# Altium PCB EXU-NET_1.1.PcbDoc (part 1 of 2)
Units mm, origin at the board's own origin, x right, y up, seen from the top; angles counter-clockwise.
Board outline 89 x 74.45 mm, 4 copper layers (Top Layer, Layer 1, Layer 2, Bottom Layer), stack 1.57 mm thick; 116 components, 84 nets, 406 pads, 488 vias.
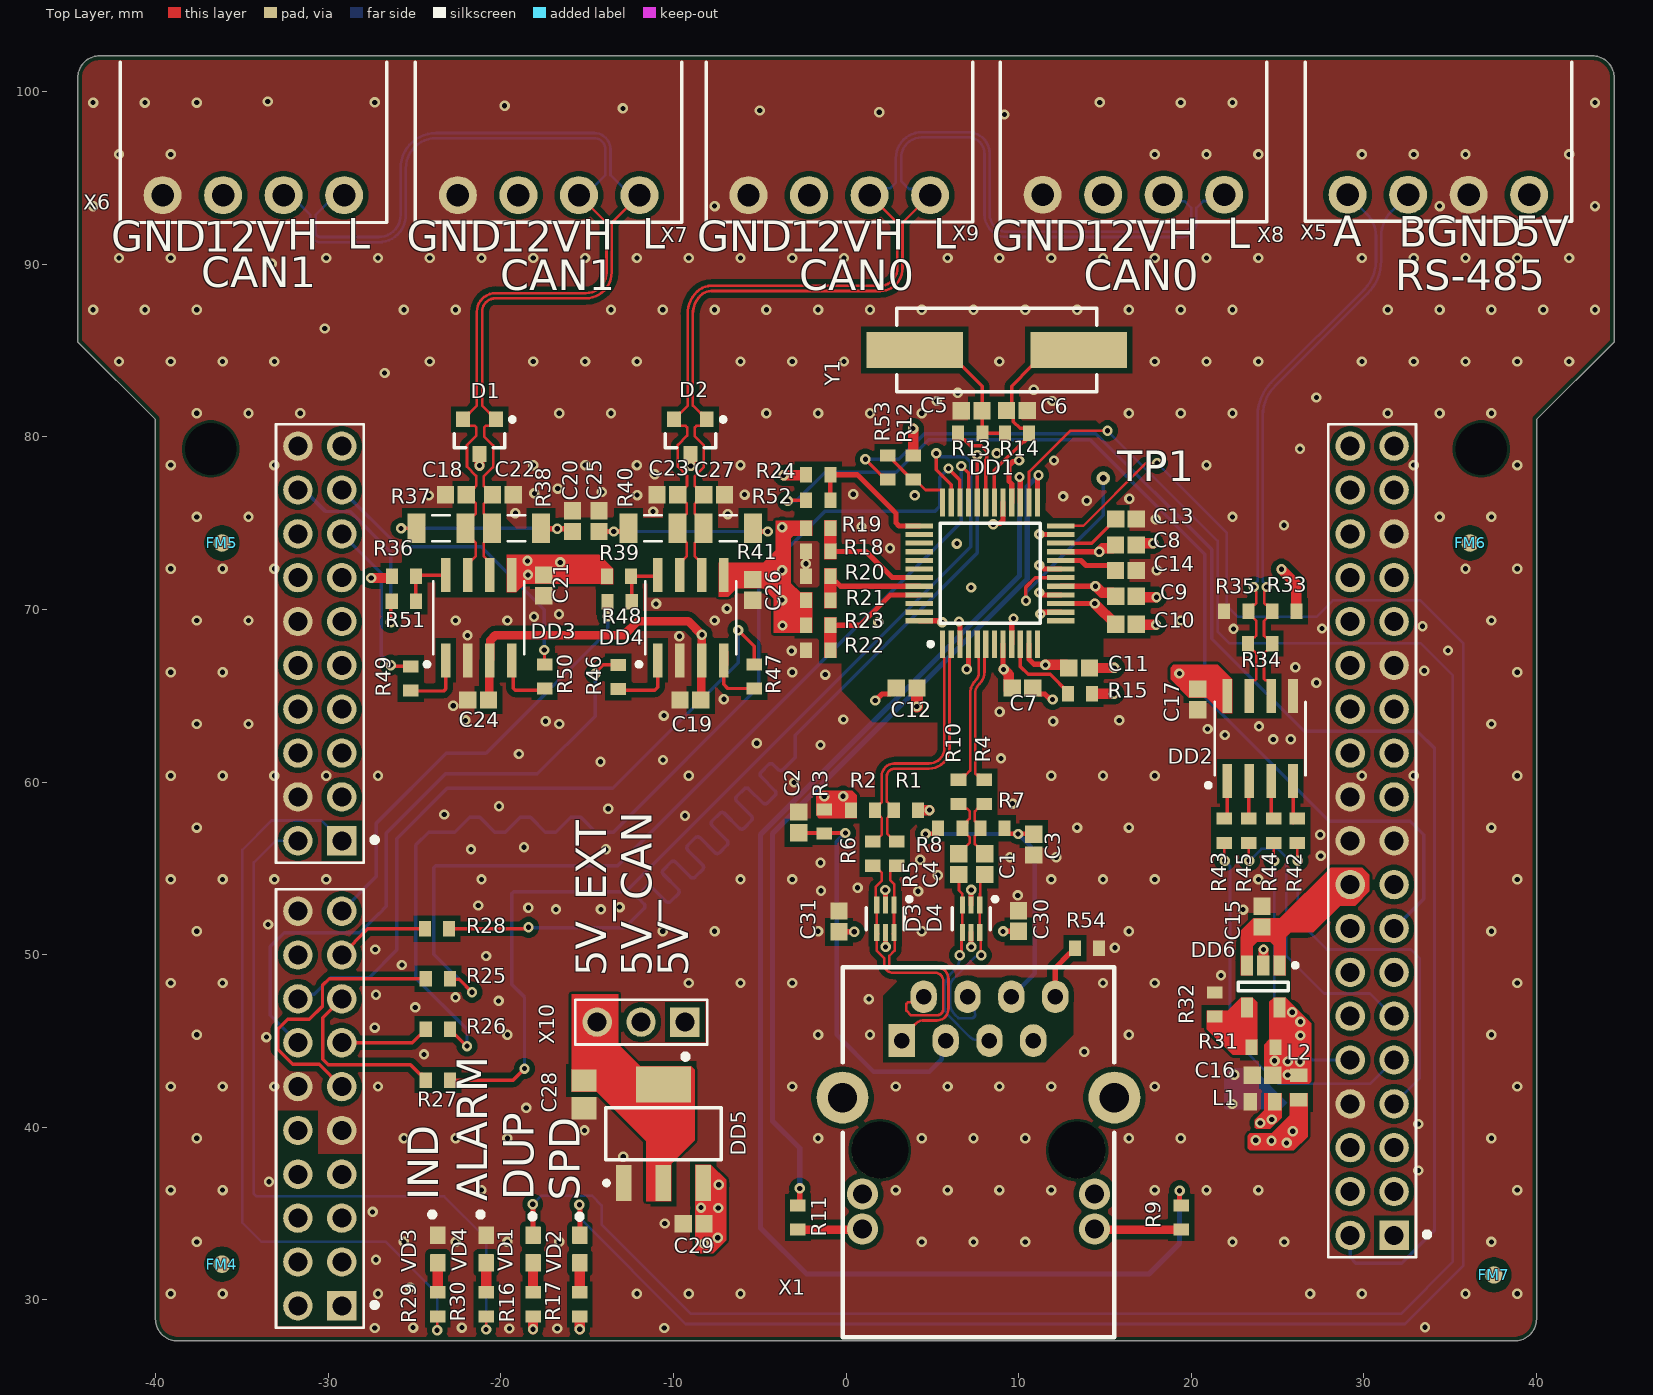
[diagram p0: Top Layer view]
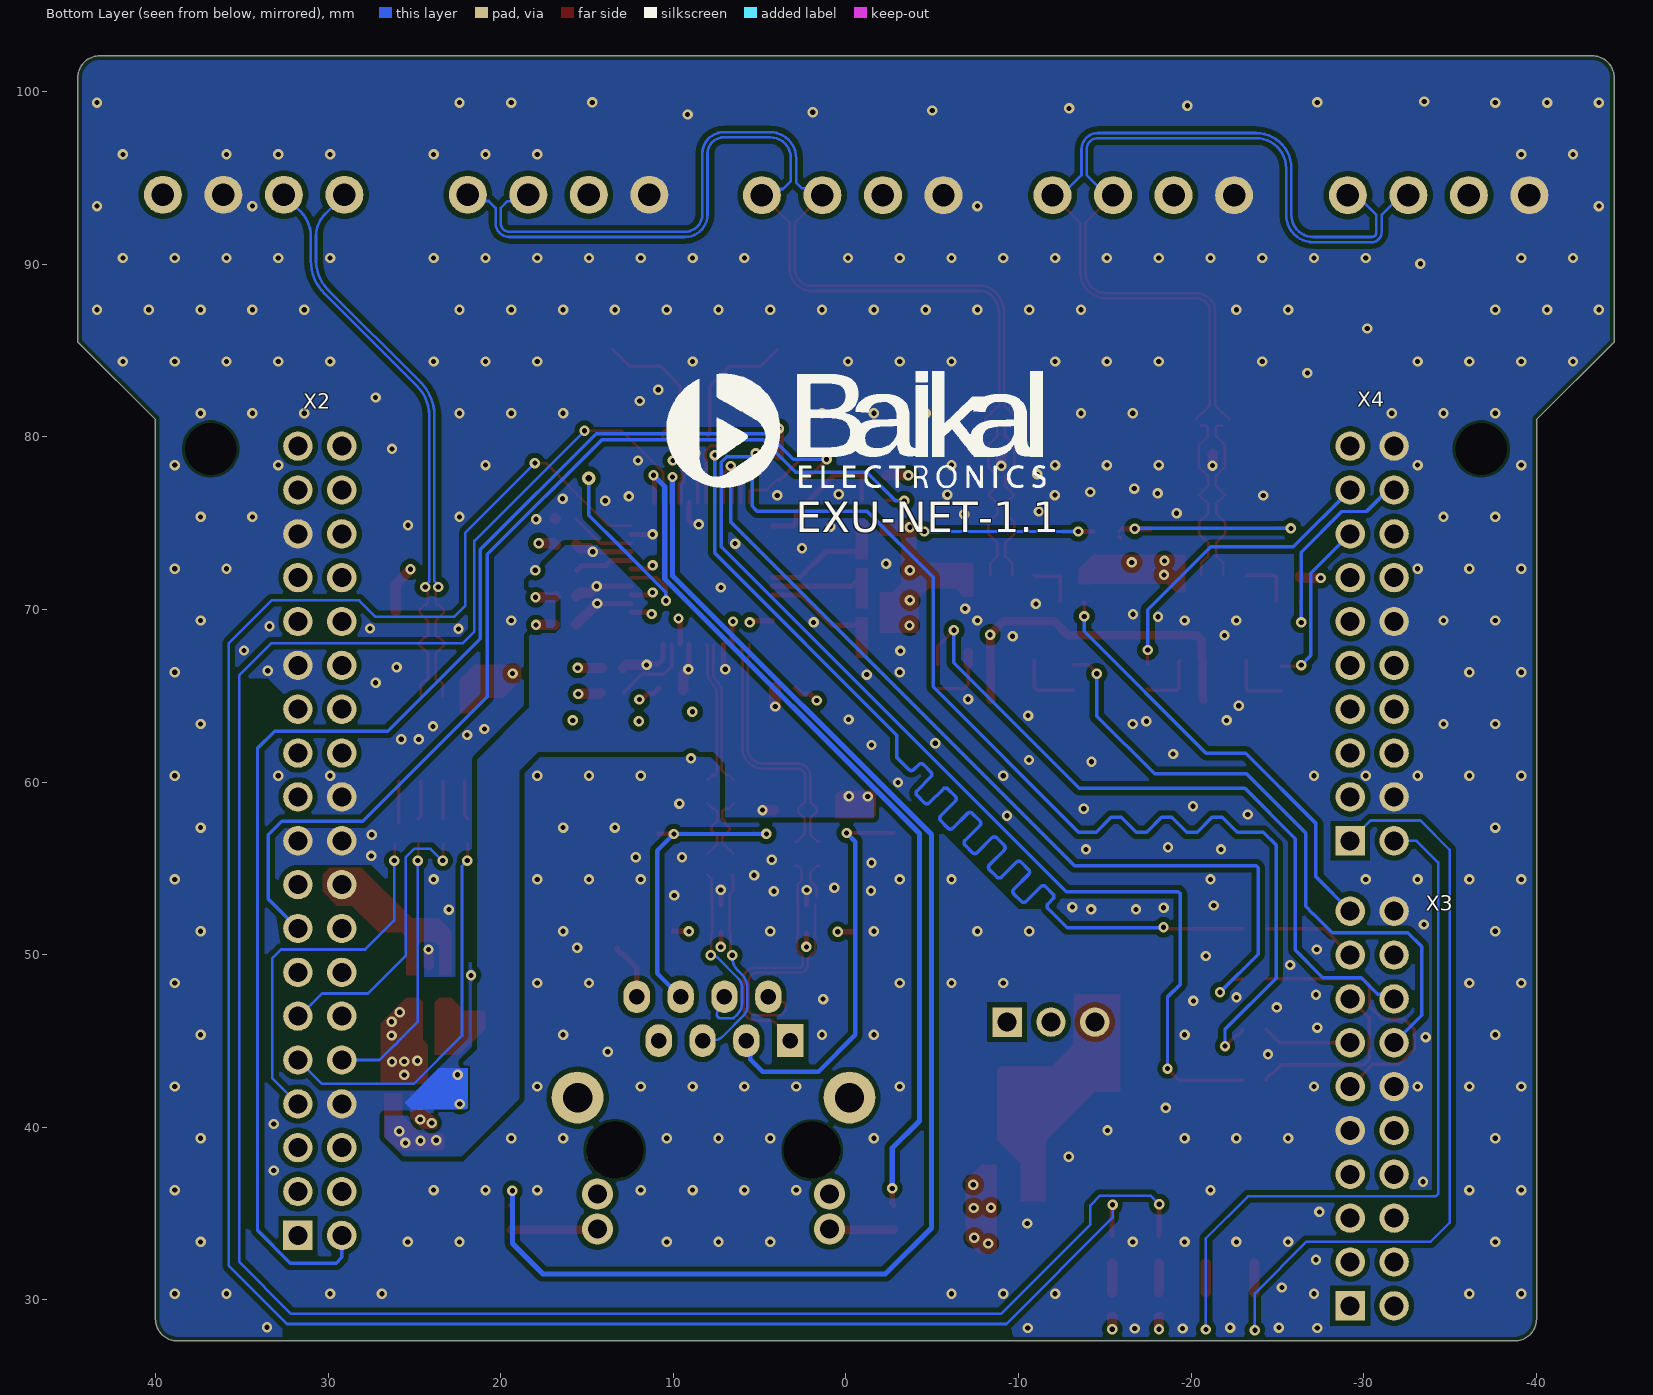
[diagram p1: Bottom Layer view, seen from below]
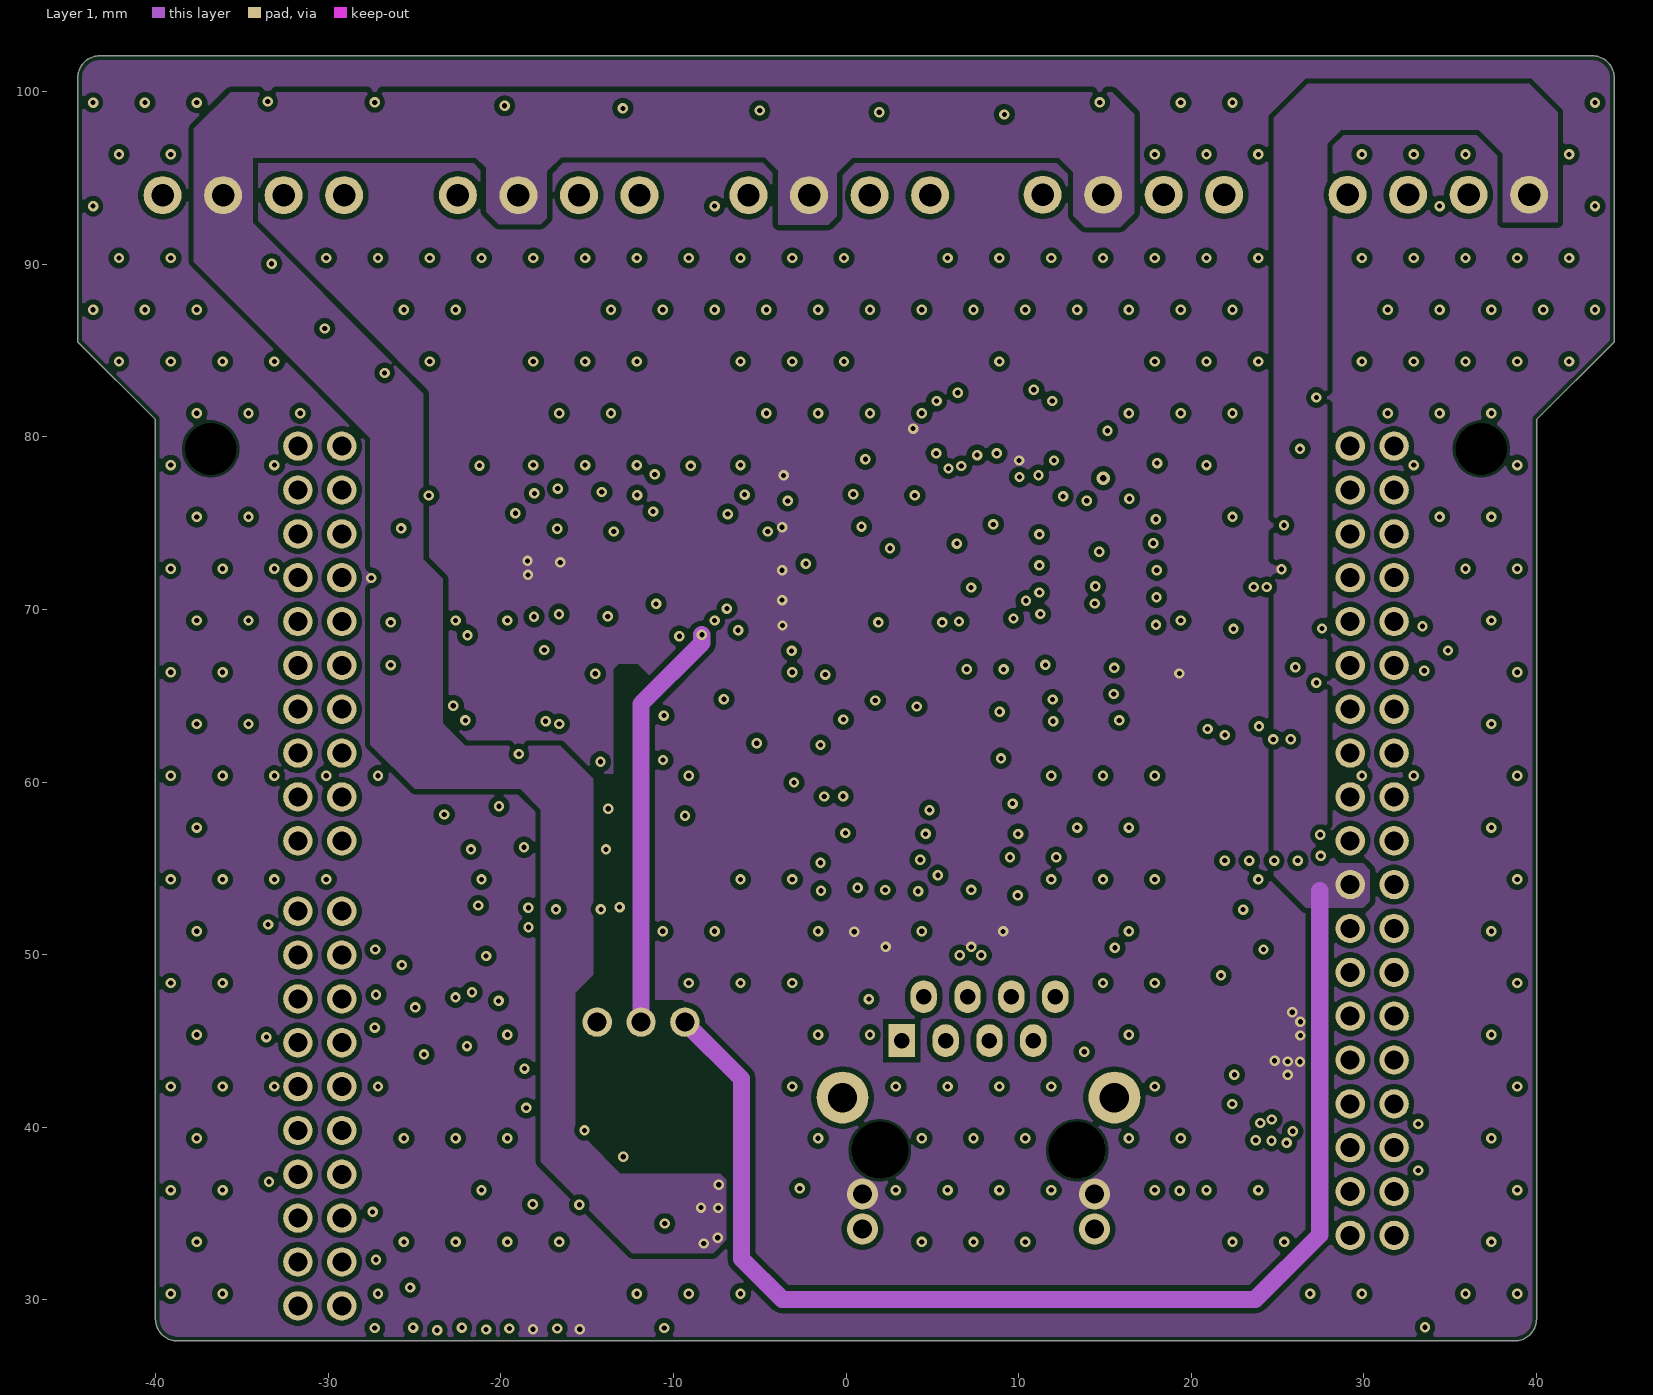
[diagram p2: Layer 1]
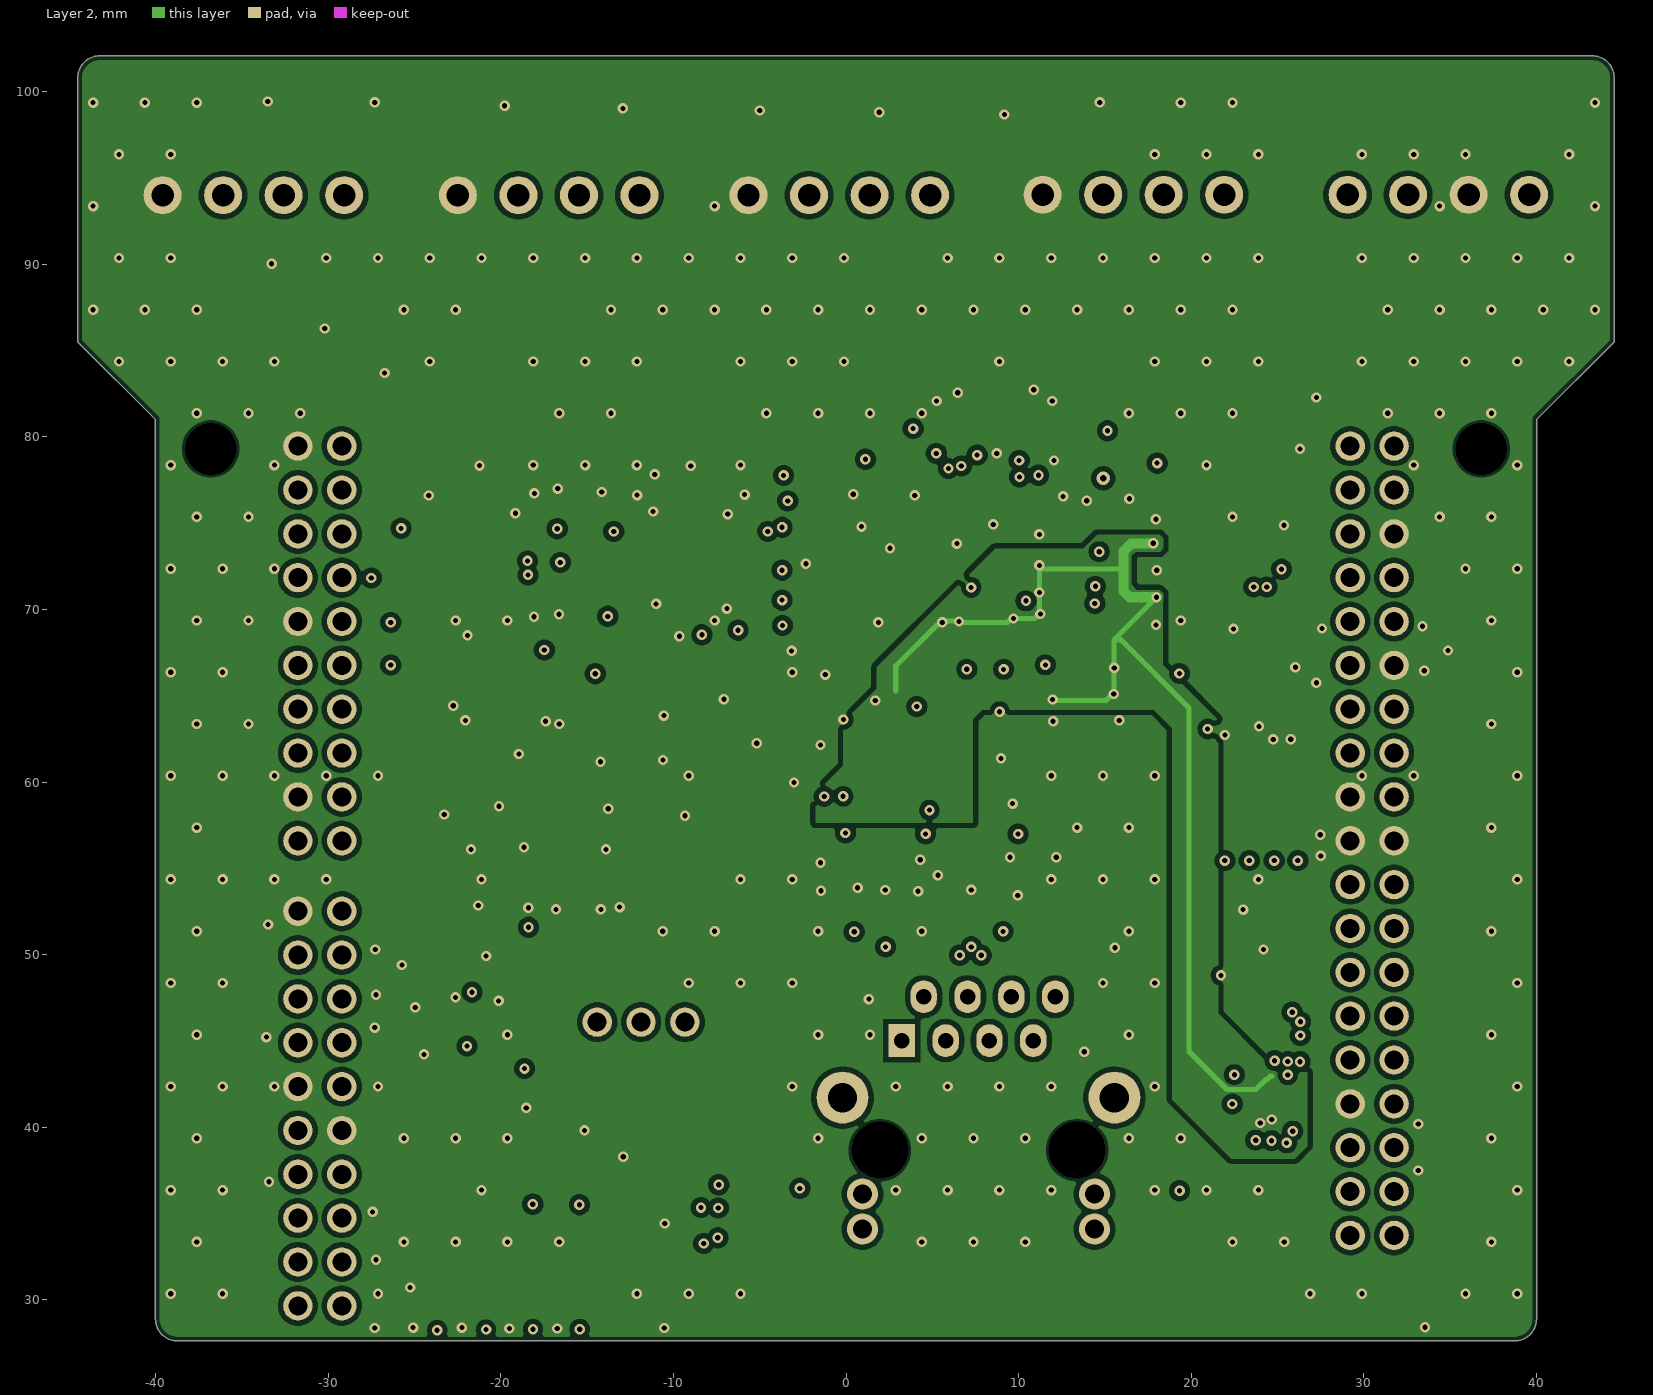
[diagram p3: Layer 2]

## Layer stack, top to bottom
Top Solder: solder mask 0.0102, Solder Resist, Dk 3.5
Top Layer: signal copper 0.035
Dielectric 2: prepreg 0.115, PP-006, Dk 4.1
Layer 1: signal copper 0.035
Dielectric 1: dielectric 1.2, FR-4, Dk 4.8
Layer 2: signal copper 0.035
Dielectric 3: prepreg 0.115, PP-006, Dk 4.1
Bottom Layer: signal copper 0.035
Bottom Solder: solder mask 0.0102, Solder Resist, Dk 3.5

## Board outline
-40,28.895 -40,29.352 -40,81 -44.5,85.5 -44.5,100.802 cw(c-43.23,100.802) -43.23,102.072 43.23,102.072 cw(c43.23,100.802) 44.5,100.802 44.5,85.5 40,81 40,29.925 40,28.895 cw(c38.73,28.895) 38.73,27.625 -38.73,27.625 cw(c-38.73,28.895)

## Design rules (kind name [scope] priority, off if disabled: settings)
BoardOutlineClearance [All] p1: gap=0.25 ignorepadtopadclearanceinfootprint=FALSE
Clearance [All] p1: gap=0.15 ignorepadtopadclearanceinfootprint=FALSE except(0.3: Arc-Poly Track-Poly SMDPad-Poly THPad-Poly Via-Poly Fill-Poly Poly-Poly)
DiffPairsRouting DiffPairsRouting_1 [InDifferentialPairClass('120')] p1: maxlimit=5 minlimit=0.3 mostfreqgap=0.3 toplayer_minwidth=0.15 toplayer_maxwidth=0.15 toplayer_prefwidth=0.15 midlayer1_minwidth=0.15 midlayer1_maxwidth=0.15 midlayer1_prefwidth=0.15 midlayer2_minwidth=0.15 midlayer2_maxwidth=0.15 midlayer2_prefwidth=0.15 bottomlayer_minwidth=0.15 bottomlayer_maxwidth=0.15 bottomlayer_prefwidth=0.15 maxuncoupledlength=12.7
DiffPairsRouting [InDifferentialPairClass('USB')] p2: maxlimit=1 minlimit=0.15 mostfreqgap=0.15 toplayer_minwidth=0.15 toplayer_maxwidth=0.15 toplayer_prefwidth=0.15 midlayer1_minwidth=0.15 midlayer1_maxwidth=0.15 midlayer1_prefwidth=0.15 midlayer2_minwidth=0.15 midlayer2_maxwidth=0.15 midlayer2_prefwidth=0.15 bottomlayer_minwidth=0.15 bottomlayer_maxwidth=0.15 bottomlayer_prefwidth=0.15 maxuncoupledlength=12.7
HoleSize [All] p1: absolutevalues=TRUE maxlimit=10 minlimit=0.025 maxpercent=80.000 minpercent=20.000
HoleToHoleClearance [All] p1: gap=0.2 allowstackedmicrovias=TRUE
MatchedLengths [InxSignalClass('100Om')] p1: tolerance=1.5 checknetsindiffpair=TRUE checkdiffpairvsdiffpair=FALSE checkxsignals=FALSE checkothers=FALSE
MatchedLengths SPI [InxSignalClass('SPI')] p2: tolerance=3.8 checknetsindiffpair=FALSE checkdiffpairvsdiffpair=TRUE checkxsignals=TRUE checkothers=TRUE targetsourcename=SCLK-SPI
MatchedLengths ETH [InxSignalClass('100Om')] p3: tolerance=0.5 checknetsindiffpair=FALSE checkdiffpairvsdiffpair=TRUE checkxsignals=TRUE checkothers=TRUE
MinimumSolderMaskSliver [All] p1: minsoldermaskwidth=0.1
PolygonConnect [All] p1: connectstyle=Direct reliefconductorwidth=0.254 reliefentries=4 polygonreliefangle="90 Angle" airgapwidth=0.254
RoutingVias [All] p1: holewidth=0.3 width=0.6 viastyle="Through Hole" minholewidth=0.2 minwidth=0.3 maxholewidth=0.6 maxwidth=1
SilkToSilkClearance [All] p1: silktosilkclearance=0.1
SilkToSolderMaskClearance [IsPad] p1: minsilkscreentomaskgap=0 clearancetoexposedcopper=TRUE
SolderMaskExpansion [All] p1: expansion=0.1 istentingtop=FALSE
SupplyNets "Schematic Supply Nets_8" [InNet('TP1')] p1: voltage=0.000
SupplyNets "Schematic Supply Nets_4" [InNet('5V_EXT')] p2: voltage=0.000
SupplyNets "Schematic Supply Nets_2" [InNet('5V_CAN')] p3: voltage=0.000
SupplyNets "Schematic Supply Nets_1" [InNet('12V')] p4: voltage=0.000
SupplyNets "Schematic Supply Nets_7" [InNet('3V3A')] p5: voltage=0.000
SupplyNets "Schematic Supply Nets_6" [InNet('3V3')] p6: voltage=0.000
SupplyNets "Schematic Supply Nets_5" [InNet('GND')] p7: voltage=0.000
SupplyNets "Schematic Supply Nets_3" [InNet('AGND')] p8: voltage=0.000
SupplyNets "Schematic Supply Nets" [InNet('5V')] p9: voltage=0.000
Width [All] p1: maxlimit=1 minlimit=0.15 preferedwidth=0.2
24 further rules are at their usual default settings.

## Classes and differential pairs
differential pair class NewClass: RX RX0 RX1 TX TX0
component class Designator: C17 C18 C19 C20 C21 C22 C23 C24 C25 C26 C27 D1 D2 DD2 DD3 DD4 R33 R34 R35 R36 R37 R38 R39 R40 R41 X5 X6 X7 X8 X9 X10
component class SPI/Ethernet: C1 C2 C3 C4 C5 C6 C7 C8 C9 C10 C11 C12 C13 C14 C30 C31 D3 D4 DD1 L1 R1 R2 R3 R4 R5 R6 R7 R8 R9 R10 R11 R12 R13 R14 R15 R16 R17 R18 R19 R20 R21 R22 R23 R53 R54 VD1 VD2 X1 Y1
component class Connectors: C15 C16 C28 C29 DD5 DD6 L2 LD1 LD2 R24 R25 R26 R27 R28 R29 R30 R31 R32 R42 R43 R44 R45 R46 R47 R48 R49 R50 R51 R52 VD3 VD4 X2 X3 X4
differential pair RS485: +RS485_P -RS485_N
differential pair CAN1: +CAN1_P -CAN1_N
differential pair CAN0: +CAN0_P -CAN0_N
differential pair RX1: +RX1_P -RX1_N
differential pair TX: +TX_P -TX_N
differential pair TX0: +TX0_P -TX0_N
differential pair RX: +RX_P -RX_N
differential pair RX0: +RX0_P -RX0_N

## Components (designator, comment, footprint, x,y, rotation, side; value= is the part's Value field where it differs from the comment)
C1 "6.8nF" C0603_CAPC1608X09N#1 8.031,55.243 r270 top
C2 "22nF" C0603_CAPC1608X09N#1 -2.742,57.667 r90 top
C3 "10nF" C0603_CAPC1608X09N#1 10.873,56.381 r270 top
C4 "6.8nF" C0603_CAPC1608X09N#1 6.529,55.243 r270 top
C5 "18pF" C0603_CAPC1608X09N#1 7.281,81.512 r180 top
C6 "18pF" C0603_CAPC1608X09N#1 9.9,81.527 r0 top
C7 "10nF" C0603_CAPC1608X09N#2 10.225,65.455 r180 top
C8 "10nF" C0603_CAPC1608X09N#1 16.217,73.739 r180 top
C9 "10nF" C0603_CAPC1608X09N#1 16.219,70.767 r180 top
C10 "10nF" C0603_CAPC1608X09N#1 16.219,69.139 r180 top
C11 "10nF" C0603_CAPC1608X09N#1 13.511,66.612 r180 top
C12 "10nF" C0603_CAPC1608X09N#1 3.507,65.455 r0 top
C13 "10nF" C0603_CAPC1608X09N#1 16.219,75.236 r180 top
C14 "4.7uF" C0603_CAPC1608X09N#1 16.217,72.254 r180 top
C15 "2.2uF" C0603_CAPC1608X09N#2 24.099,52.203 r270 top
C16 "2.2uF" C0603_CAPC1608X09N#3 24.127,43.024 r0 top
C17 "100nF" C0603_CAPC1608X09N#2 20.375,64.792 r90 top
C18 "100pF" C0603_CAPC1608X09N#1 -22.595,76.637 r180 top
C19 "100nF" C0603_CAPC1608X09N#1 -9.015,64.758 r180 top
C20 "4.7nF" C0603_CAPC1608X09N#1 -15.837,75.113 r90 top
C21 "100nF" C0603_CAPC1608X09N#1 -17.504,71.399 r90 top
C22 "100pF" C0603_CAPC1608X09N#1 -19.88,76.637 r180 top
C23 "100pF" C0603_CAPC1608X09N#1 -10.342,76.637 r180 top
C24 "100nF" C0603_CAPC1608X09N#1 -21.305,64.758 r180 top
C25 "4.7nF" C0603_CAPC1608X09N#1 -14.304,75.113 r90 top
C26 "100nF" C0603_CAPC1608X09N#1 -5.404,71.138 r90 top
C27 "100pF" C0603_CAPC1608X09N#1 -7.636,76.637 r180 top
C28 "10uF" C0805_CAPC2012X13N -15.167,41.912 r90 top
C29 "100nF" C0603_CAPC1608X09N#2 -8.825,34.411 r0 top
C30 "100nF" C0603_CAPC1608X09N#2 9.995,51.954 r90 top
C31 "100nF" C0603_CAPC1608X09N#2 -0.4,51.925 r90 top
D1 "NUP2105LT1G" ONSC-SOT-23-3-318-08_V -21.229,80.006 r270 top
D2 "NUP2105LT1G" ONSC-SOT-23-3-318-08_V -9.015,80.006 r270 top
D3 "USBLC6-2P6" FP-SOT-666-MFG 2.281,52.082 r270 top
D4 "USBLC6-2P6" FP-SOT-666-MFG 7.245,52.082 r270 top
DD1 "W5500" W5500 8.349,72.093 r90 top
DD2 "ADM3485EARZ" TJA1042T/3/CM.118 23.991,62.514 r0 top
DD3 "TJA1042T/3/CM.118" TJA1042T/3/CM.118 -21.274,69.52 r0 top
DD4 "TJA1042T/3/CM.118" TJA1042T/3/CM.118 -8.993,69.52 r0 top
DD5 "LD1117S50TR" SOT-223_L -10.575,39.625 r90 top
DD6 "ADP1712AUJZ-R7" ADI-UJ-5_M 24.172,48.158 r270 top
FM4 "Comment" FIDUCIAL_MARK_2MM -36.15,32.075 r0 top
FM5 "Comment" FIDUCIAL_MARK_2MM -36.15,73.85 r0 top
FM6 "Comment" FIDUCIAL_MARK_2MM 36.15,73.85 r180 top
FM7 "Comment" FIDUCIAL_MARK_2MM 37.53,31.449 r0 top
L1 "BLM18PG471SN1" I0603_INDC1608X10N 24.13,41.478 r180 top
L2 "BLM18PG471SN1" I0603_INDC1608X10N 26.225,42.3 r90 top
R1 "51R" R0603_RESC1608X06N 3.467,58.367 r0 top
R2 "51R" R0603_RESC1608X06N 0.984,58.367 r180 top
R3 "10R" R0603_RESC1608X06N -1.271,57.717 r90 top
R4 "0R" R0603_RESC1608X06N 8.006,59.436 r270 top
R5 "0R" R0603_RESC1608X06N 2.931,55.854 r90 top
R6 "0R" R0603_RESC1608X06N 1.559,55.854 r90 top
R7 "82R" R0603_RESC1608X06N 8.492,57.315 r180 top
R8 "82R" R0603_RESC1608X06N 6.04,57.331 r180 top
R9 "330R" R0603_RESC1608X06N 19.415,34.776 r90 top
R10 "0R" R0603_RESC1608X06N 6.518,59.436 r270 top
R11 "330R" R0603_RESC1608X06N -2.782,34.776 r90 top
R12 "10K" R0603_RESC1608X06N 3.905,78.217 r90 top
R13 "0R" R0603_RESC1608X06N 7.198,80.196 r0 top
R14 "1M" R0603_RESC1608X06N 9.912,80.196 r180 top
R15 "12K4" R0603_RESC1608X06N 13.561,65.113 r180 top
R16 "330R" R0603_RESC1608X06N -18.129,29.744 r90 top
R17 "330R" R0603_RESC1608X06N -15.415,29.744 r90 top
R18 "10K" R0603_RESC1608X06N -1.606,73.359 r0 top
R19 "10K" R0603_RESC1608X06N -1.606,74.707 r180 top
R20 "10K" R0603_RESC1608X06N -1.606,71.928 r0 top
R21 "10K" R0603_RESC1608X06N -1.606,70.534 r180 top
R22 "10K" R0603_RESC1608X06N -1.606,67.643 r0 top
R23 "10K" R0603_RESC1608X06N -1.606,69.088 r180 top
R24 "10K" R0603_RESC1608X06N -1.606,77.803 r0 top
R25 "22R" R0603_RESC1608X06N -23.645,48.605 r180 top
R26 "22R" R0603_RESC1608X06N -23.645,45.674 r180 top
R27 "22R" R0603_RESC1608X06N -23.645,42.74 r180 top
R28 "22R" R0603_RESC1608X06N -23.695,51.497 r180 top
R29 "330R" R0603_RESC1608X06N -23.645,29.744 r270 top
R30 "1K" R0603_RESC1608X06N -20.85,29.744 r270 top
R31 "10K" R0603_RESC1608X06N 24.18,44.642 r0 top
R32 "3K3" R0603_RESC1608X06N 21.355,47.114 r270 top
R33 "750R" R0603_RESC1608X06N 25.391,69.904 r0 top
R34 "120R" R0603_RESC1608X06N 23.991,68.025 r0 top
R35 "750R" R0603_RESC1608X06N 22.607,69.904 r0 top
R36 "10K" R0603_RESC1608X06N -25.603,71.933 r180 top
R37 "59R" R1206_RESC3116X07N -23.462,74.707 r180 top
R38 "59R" R1206_RESC3116X07N -19.087,74.707 r0 top
R39 "10K" R0603_RESC1608X06N -13.147,71.917 r180 top
R40 "59R" R1206_RESC3116X07N -11.177,74.707 r180 top
R41 "59R" R1206_RESC3116X07N -6.819,74.707 r0 top
R42 "22R" R0603_RESC1608X06N 26.146,57.179 r90 top
R43 "22R" R0603_RESC1608X06N 21.915,57.179 r90 top
R44 "22R" R0603_RESC1608X06N 24.78,57.179 r90 top
R45 "22R" R0603_RESC1608X06N 23.338,57.179 r90 top
R46 "22R" R0603_RESC1608X06N -13.191,66.087 r90 top
R47 "22R" R0603_RESC1608X06N -5.319,66.12 r90 top
R48 "22R" R0603_RESC1608X06N -13.113,70.449 r180 top
R49 "22R" R0603_RESC1608X06N -25.208,66.002 r90 top
R50 "22R" R0603_RESC1608X06N -17.464,66.12 r90 top
R51 "22R" R0603_RESC1608X06N -25.613,70.47 r180 top
R52 "0R" R0603_RESC1608X06N -1.606,76.313 r0 top
R53 "0R" R0603_RESC1608X06N 2.414,78.227 r270 top
R54 "0R" R0603_RESC1608X06N 13.954,50.369 r0 top
VD1 "KPT-1608SGC" "LIGHT DIODE 0603" -18.129,32.95 r90 top
VD2 "KPT-1608SGC" "LIGHT DIODE 0603" -15.415,32.95 r90 top
VD3 "KPT-1608SGC" "LIGHT DIODE 0603" -23.645,32.95 r90 top
VD4 "KPT-1608SRC-PRV" "LIGHT DIODE 0603" -20.85,32.95 r90 top
X1 "TRJ16093BENL" TRJ16093BENL 7.675,38.675 r0 top
X2 "38_PIN_HEADER_M" 38_PIN_HEADER_M 30.48,56.6 r90 bottom locked
X3 "20_PIN_HEADER_M" 20_PIN_HEADER_M -30.48,41.09 r90 bottom
X4 "20_PIN_HEADER_M" 20_PIN_HEADER_M -30.48,68.03 r90 bottom locked
X5 "15EDGRC-3.5-04P-14-00A(H)" 15EDGRC-3.5-04P-14-00A(H) 34.315,97.325 r270 top
X6 "15EDGRC-3.5-04P-14-00A(H)" 15EDGRC-3.5-04P-14-00A(H) -34.332,97.3 r270 top
X7 "15EDGRC-3.5-04P-14-00A(H)" 15EDGRC-3.5-04P-14-00A(H) -17.223,97.3 r270 top
X8 "15EDGRC-3.5-04P-14-00A(H)" 15EDGRC-3.5-04P-14-00A(H) 16.652,97.325 r270 top
X9 "15EDGRC-3.5-04P-14-00A(H)" 15EDGRC-3.5-04P-14-00A(H) -0.387,97.3 r270 top
X10 "3_PIN_HEADER_254" 3_PIN_HEADER_254 -10.602,46.096 r180 top
Y1 "25MHz" SJK-6C-25.000-16-30-30-C-50-H 8.737,85.033 r180 top

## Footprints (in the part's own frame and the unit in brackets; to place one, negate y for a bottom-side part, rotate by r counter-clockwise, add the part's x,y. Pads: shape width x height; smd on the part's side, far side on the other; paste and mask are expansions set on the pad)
3_PIN_HEADER_254 [mm] "2.54mm Pitch Pin Header, 1 Row, 3 Circuits, Through Hole, Vertical, Gold"
  rect 1.7x1.7 / inner round 1.7 / far side rect 1.7x1.7 hole 1.1: 1(-1.27,0)
  round 1.7 hole 1.1 mask+0.1: 2(1.27,0) 3(3.81,0)
  silkscreen extent -2.56,-1.3 5.08,2.15, body extent -2.54,-1.27 5.06,1.27, height 9.5
15EDGRC-3.5-04P-14-00A(H) [mil]
  round 86.61 hole 51: 1(130,-207) 2(130,-69) 3(130,69) 4(130,207)
  silkscreen extent -172,-304 191,304, body extent -180,-304 180,304, height 280
20_PIN_HEADER_M [mm]
  rect 1.7x1.7 / inner round 1.7 / far side rect 1.7x1.7 hole 1.1: 1(-11.43,1.27)
  round 1.7 hole 1.1: 2(-11.43,-1.27)
  round 1.7 hole 1.1 mask+0.1: 3(-8.89,1.27) 4(-8.89,-1.27) 5(-6.35,1.27) 6(-6.35,-1.27) 7(-3.81,1.27) 8(-3.81,-1.27) 9(-1.27,1.27) 10(-1.27,-1.27) 11(1.27,1.27) 12(1.27,-1.27) 13(3.81,1.27) 14(3.81,-1.27) 15(6.35,1.27) 16(6.35,-1.27) 17(8.89,1.27) 18(8.89,-1.27) 19(11.43,1.27) 20(11.43,-1.27)
  body extent -12.7,-2.54 12.7,2.54, height 2
38_PIN_HEADER_M [mm]
  rect 1.7x1.7 / inner round 1.7 / far side rect 1.7x1.7 hole 1.1: 1(-22.86,1.27)
  round 1.7 hole 1.1: 2(-22.86,-1.27)
  round 1.7 hole 1.1 mask+0.1: 3(-20.32,1.27) 4(-20.32,-1.27) 5(-17.78,1.27) 6(-17.78,-1.27) 7(-15.24,1.27) 8(-15.24,-1.27) 9(-12.7,1.27) 10(-12.7,-1.27) 11(-10.16,1.27) 12(-10.16,-1.27) 13(-7.62,1.27) 14(-7.62,-1.27) 15(-5.08,1.27) 16(-5.08,-1.27) 17(-2.54,1.27) 18(-2.54,-1.27) 19(0,1.27) 20(0,-1.27) 21(2.54,1.27) 22(2.54,-1.27) 23(5.08,1.27) 24(5.08,-1.27) 25(7.62,1.27) 26(7.62,-1.27) 27(10.16,1.27) 28(10.16,-1.27) 29(12.7,1.27) 30(12.7,-1.27) 31(15.24,1.27) 32(15.24,-1.27) 33(17.78,1.27) 34(17.78,-1.27) 35(20.32,1.27) 36(20.32,-1.27) 37(22.86,1.27) 38(22.86,-1.27)
  body extent -24.13,-2.54 24.13,2.54, height 2
ADI-UJ-5_M [mm] "SOT23, 5-Leads, Body 2.9x1.6mm, Pitch 0.95mm, IPC Low Density"
  rect 1.15x0.7 smd mask+0: 1(-1.225,0.95) 2(-1.225,0) 3(-1.225,-0.95)
  rect 1.15x0.7 smd: 4(1.225,-0.95) 5(1.225,0.95)
  silkscreen extent -1.35,-1.45 0.25,1.98, body extent -0.8,-1.45 0.8,1.45, height 1
C0603_CAPC1608X09N#1 [mm] "0603, Chip Capacitor, 2-Leads, Body 1,60x0,80mm, IPC Medium Density"
  rect 1x1 smd mask+0.01: 1(-0.6,0) 2(0.6,0)
  body extent -0.9,-0.5 0.9,0.5, height 0.95
C0603_CAPC1608X09N#2 [mm] "0603, Chip Capacitor, 2-Leads, Body 1,60x0,80mm, IPC Medium Density"
  rect 1x1 smd: 1(-0.6,0) 2(0.6,0)
  body extent -0.9,-0.5 0.9,0.5, height 0.95
C0603_CAPC1608X09N#3 [mm] "0603, Chip Capacitor, 2-Leads, Body 1,60x0,80mm, IPC Medium Density"
  rect 1x1 smd mask+0: 1(-0.6,0) 2(0.6,0)
  body extent -0.9,-0.5 0.9,0.5, height 0.95
C0805_CAPC2012X13N [mm] "0805, Chip Capacitor, 2-Leads, Body 2,00x1,25mm, IPC Medium Density"
  rect 1.3x1.45 smd: 1(-0.8,0) 2(0.8,0)
  body extent -1.1,-0.72 1.1,0.72, height 1.27
FIDUCIAL_MARK_2MM [mil]
  round 40 smd paste-99999 mask+20: 1(0,0)
  Top Layer pour cut-out: 0,-40 -15.31,-36.96 -28.28,-28.28 -36.96,-15.31 -40,0 -40,0 -36.96,15.31 -28.28,28.28 -15.31,36.95 0,40 0,40 15.31,36.96 28.28,28.28 36.96,15.31 40,0 40,0 34.64,-20 20,-34.64 0,-40
FP-SOT-666-MFG [mm]
  rect 0.99x0.3 smd paste+0 mask+0: 1(-0.805,0.5) 2(-0.805,0) 3(-0.805,-0.5) 4(0.805,-0.5) 5(0.805,0) 6(0.805,0.5)
  silkscreen extent -1.26,-1.1 0.65,1.51, body extent -1.4,-0.95 1.4,0.95, height 0.25
I0603_INDC1608X10N [mm] "0603, Chip Inductor, 2-Leads, Body 1,60x0,80mm, IPC Medium Density"
  rect 0.78x1.02 smd: 1(-0.71,0) 2(0.71,0)
  body extent -0.9,-0.5 0.9,0.5, height 1
"LIGHT DIODE 0603" [mm]
  rrect5% 1x0.9 smd mask+0.07: 1(-0.8,0) 2(0.8,0)
  silkscreen extent 1.74,-0.12 2.04,0.18, body extent -0.8,-0.4 0.8,0.4, height 0.76
ONSC-SOT-23-3-318-08_V [mm] "SOT23, 3-Leads, Body 2.92x1.3mm, Pitch 0.95mm"
  rect 0.9x0.8 smd: 1(-1,0.95) 2(-1,-0.95) 3(1,0)
  silkscreen extent -1.12,-1.46 0.65,2.03, body extent -0.65,-1.46 0.65,1.46, height 1.11
R0603_RESC1608X06N [mm] "0603, Chip Resistor, 2-Leads, Body 1,60x0,80mm, IPC Medium Density"
  rect 0.7x0.9 smd: 1(-0.7,0) 2(0.7,0)
  body extent -0.85,-0.45 0.85,0.45, height 0.55
R1206_RESC3116X07N [mm] "1206, Chip Resistor, 2-Leads, Body 3,10x1,60mm, IPC Medium Density"
  rect 1.05x1.7 smd: 1(-1.425,0) 2(1.425,0)
  silkscreen extent -0.5,-0.75 0.5,0.75, body extent -1.6,-0.85 1.6,0.85, height 0.65
SJK-6C-25.000-16-30-30-C-50-H [mm]
  rect 5.6x2.1 smd paste+0 mask+0: 1(-4.75,0) 2(4.75,0)
  silkscreen extent -5.8,-2.42 5.8,2.42, body extent -6.35,-2.35 6.35,2.35, height 3.3
SOT-223_L [mm] "SOT223, 4-Leads, Body 6.5x3.5mm, Pitch 2.3mm, Lead Span 7mm, IPC High Density"
  rect 2.1x0.9 smd: 1(-2.85,2.3) 2(-2.85,0) 3(-2.85,-2.3)
  rect 2.1x3.2 smd: 4(2.85,0)
  silkscreen extent -2.97,-3.35 1.5,3.42, body extent -1.85,-3.35 1.85,3.35, height 1.8
TJA1042T/3/CM.118 [mm] "Description"
  rect 0.558x1.97 smd paste+0 mask+0: 1(-1.905,-2.464) 2(-0.635,-2.464) 3(0.635,-2.464) 4(1.905,-2.464) 5(1.905,2.464) 6(0.635,2.464) 7(-0.635,2.464) 8(-1.905,2.464)
  silkscreen extent -3.12,-2.82 2.63,2.12, body extent -2.5,-3.1 2.5,3.1, height 1.76
TRJ16093BENL [mm] "Connector ecr. \"socket\" RJ-45 C matching. 10/100Base-TX filter (1:1), 2 tops. the LED. (left green/right yellow), without petals, -40 to + 85 °C, etc. angle per board, Lc = 21.5 mm"
  rect 1.525x1.9 hole 0.9: 1(-4.445,6.35)
  oval 1.525x1.9 hole 0.9: 2(-3.175,8.89) 3(-1.905,6.35) 4(-0.635,8.89) 5(0.635,6.35) 6(1.905,8.89) 7(3.175,6.35) 8(4.445,8.89)
  round 1.8 hole 1.1: 9(6.725,-2.54) 10(6.725,-4.57) 11(-6.725,-2.54) 12(-6.725,-4.57)
  round 3.251 hole 3.3 unplated: DNC(-5.715,0) DNC(5.715,0)
  round 3 hole 1.7: MH(-7.874,3.048) MH(7.874,3.048)
  silkscreen extent -7.86,-10.85 7.86,10.59, body extent -8,-10.91 8,10.59, height 14.6
W5500 [mm]
  rect 1.6x0.3 smd: 1(-4.1,2.75) 2(-4.1,2.25) 3(-4.1,1.75) 4(-4.1,1.25) 5(-4.1,0.75) 6(-4.1,0.25) 7(-4.1,-0.25) 8(-4.1,-0.75) 9(-4.1,-1.25) 10(-4.1,-1.75) 11(-4.1,-2.25) 12(-4.1,-2.75) 25(4.1,-2.75) 26(4.1,-2.25) 27(4.1,-1.75) 28(4.1,-1.25) 29(4.1,-0.75) 30(4.1,-0.25) 31(4.1,0.25) 32(4.1,0.75) 33(4.1,1.25) 34(4.1,1.75) 35(4.1,2.25) 36(4.1,2.75)
  rect 0.3x1.6 smd: 13(-2.75,-4.1) 14(-2.25,-4.1) 15(-1.75,-4.1) 16(-1.25,-4.1) 17(-0.75,-4.1) 18(-0.25,-4.1) 19(0.25,-4.1) 20(0.75,-4.1) 21(1.25,-4.1) 22(1.75,-4.1) 23(2.25,-4.1) 24(2.75,-4.1) 37(2.75,4.1) 38(2.25,4.1) 39(1.75,4.1) 40(1.25,4.1) 41(0.75,4.1) 42(0.25,4.1) 43(-0.25,4.1) 44(-0.75,4.1) 45(-1.25,4.1) 46(-1.75,4.1) 47(-2.25,4.1) 48(-2.75,4.1)
  silkscreen extent -4.22,-2.9 2.9,3.57, body extent -4.5,-4.5 4.5,4.5, height 1.6

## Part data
C1 C4: library part CC0603KRX7R9BB682, "0603 6,8nF ±10% 50V", Manufacturer=YAGEO, ValueBOM="6800пФ ±10% 50В X7R 0603", ValueSCH="6800 50V"
C2: library part CC0603KRX7R9BB223, "0603 22nF ±10% 50V", Manufacturer=YAGEO, ValueBOM="0,022мкФ ±10% 50В X7R 0603", ValueSCH="0,022u 50V"
C3 C7 C8 C9 C10 C11 C12 C13: library part CC0603KRX7R9BB103, "0603 10nF ±10% 50V", Manufacturer=YAGEO, ValueBOM="0,01мкФ ±10% 50В X7R 0603"
C5 C6: library part CC0603JRNPO9BN180, "0603 18pF ±10% 50V", Manufacturer=YAGEO, ValueBOM="18пФ ±5% 50В NP0 0603", ValueSCH="18 50V"
C14: library part CC0603KRX7R5BB475, "0603 4,7uF ±10% 6,3V", Manufacturer=YAGEO, ValueBOM="4,7мкФ ±10% 6,3В X7R 0603", ValueSCH="4,7u 6,3V"
C15 C16: library part CC0603KRX7R7BB225, "0603 2,2uF ±10% 16V", Manufacturer=YAGEO, ValueBOM="2,2мкФ ±10%", ValueSCH="2,2u 16V"
C17 C19 C21 C24 C26 C29 C30 C31: library part CC0603KRX7R9BB104, "0603 100nF ±10% 50V", Manufacturer=YAGEO, ValueBOM="0,1мкФ ±10% 50В X7R 0603"
C18 C22 C23 C27: library part CC0603KRX7R9BB101, "0603 100pF  ±10% 50V", Manufacturer=YAGEO, ValueBOM="100пФ ±10% 50В X7R 0603", ValueSCH="100 50V"
C20 C25: library part CC0603KRX7R9BB472, "0603 4,7nF ±10% 50V", Manufacturer=YAGEO, ValueBOM="4700пФ ±10% 50В X7R 0603", ValueSCH="4700 50V"
C28: library part CC0805KRX7R7BB106, "Конденсатор керамический (MLCC) общего назначения 0805", Manufacturer=YAGEO, ValueBOM="10мкФ ±10% 16В X7R 0805", ValueSCH="10u 16V"
D1 D2: library part CMP-1063-00164-1, "Dual Line CAN Bus Protector, 3-Pin SOT-23, Pb-Free, Tape and Reel", Manufacturer="On Semiconductor"
D3 D4: library part CMP-12225-000058-1, "TVS DIODE 5.25V 17V SOT666", Breakdown Voltage=6V, Capacitance=3.5pF, Case/Package=SOT-666, Clamping Voltage=17V, Leakage Current=150nA, Max Operating Temperature=125°C, Min Operating Temperature=-40°C, Operating Supply Voltage=5V, Package Quantity=1, Peak Pulse Current=5A, Power Line Protection=Yes, Test Current=1mA
DD1: "W5500, TCP/IP Ethernet Controller IC, [LQFP-48]"
DD2: "3.3 V, Â±15 kV ESD-Protected, RS-485/RS-422 Transceiver (Half Duplex, 12Mbps, DE/RE)", Manufacturer="Youtai Semiconductor (UMW)"
DD3 DD4: "Can interface, SOIC8", Manufacturer="NXP Semiconductor"
DD5: library part CMP-0244-00312-1, "Fixed Low Drop Positive Voltage Regulator, 5V, 4-Pin SOT-223, Tape and Reel"
DD6: library part CMP-0786-00408-1, "300 mA, Low Dropout CMOS Linear Regulator, 2.5 to 5.5 V Vin, 0.8 to 5 V Vout, Industrial, 5-pin SOT23 (UJ-5), Reel", Manufacturer="Analog Devices", Supply Current IGND @ Small Load=60uA
L1 L2: "EMI Inductive Filter for Power lines 470Ohm 25% 100MHz 1A 200mOhm DCR 0603 T/R", Manufacturer=Murata
R1 R2: library part RC0603JR-0751RL, "0603 51 Ohm±5% 0,1W", Manufacturer=YAGEO, ValueBOM="51Ом   75В 200ppm 0603"
R3: library part RC0603JR-0710RL, "0603 10 Ohm±5% 0,1W", Manufacturer=YAGEO, ValueBOM="10Ом   75В 300ppm 0603"
R4 R5 R6 R10 R13 R52 R53 R54: library part RC0603JR-070RL, "0603 0 Ohm 0,1W", Manufacturer=YAGEO, ValueBOM="0Ом   75В 300ppm 0603"
R7 R8: library part RC0603JR-0782RL, "0603 82 Ohm±5% 0,1W", Manufacturer=YAGEO, ValueBOM="82Ом   75В 200ppm 0603"
R9 R11 R16 R17 R29: library part RC0603JR-07330RL, "0603 330 Ohm±5% 0,1W", Manufacturer=YAGEO, ValueBOM="330Ом   75В 150ppm 0603"
R12 R18 R19 R20 R21 R22 R23 R24 R31 R36 R39: library part RC0603JR-0710KL, "0603 10 kOhm±5% 0,1W", Manufacturer=YAGEO, ValueBOM="10кОм   75В 150ppm 0603"
R14: library part RC0603JR-071ML, "0603 1 MOhm±5% 0,1W", Manufacturer=YAGEO, ValueBOM="1МОм   75В 150ppm 0603"
R15: library part RC0603FR-0712K4L, "0603 12,4 kOhm±1% 0,1W", Manufacturer=YAGEO, ValueBOM="12,4кОм   75В 150ppm 0603", ValueSCH=12,4K
R25 R26 R27 R28 R42 R43 R44 R45 R46 R47 R48 R49 R50 R51: library part RC0603JR-0722RL, "0603 22 Ohm±5% 0,1W", Manufacturer=YAGEO, ValueBOM="22Ом   75В 200ppm 0603"
R30: library part RC0603JR-071KL, "0603 1 kOhm±5% 0,1W", Manufacturer=YAGEO, ValueBOM="1кОм   75В 150ppm 0603"
R32: library part RC0603JR-073K3L, "0603 3,3 kOhm±5% 0,1W", Manufacturer=YAGEO, ValueBOM="3,3кОм   75В 150ppm 0603", ValueSCH=3,3K
R33 R35: library part RC0603JR-07750RL, "0603 750 Ohm±5% 0,1W", Manufacturer=YAGEO, ValueBOM="750Ом   75В 150ppm 0603"
R34: library part RC0603JR-07120RL, "0603 120 Ohm±5% 0,1W", Manufacturer=YAGEO, ValueBOM="120Ом   75В 150ppm 0603"
R37 R38 R40 R41: library part RC1206FR-0759RL, "1206 59 Ohm±1% 0,1W", Manufacturer=YAGEO, ValueBOM="59Ом 1% 200В 100ppm 1206", ValueSCH="59 1%"
VD1 VD2 VD3: "Green LED SMD 0603"
VD4: "Red LED SMD 0603"
X1: "Connector ecr. \"socket\" RJ-45 C matching. 10/100Base-TX filter (1:1), 2 tops. the LED. (left green/right yellow), without petals, -40 to + 85 °C, etc. angle per board, Lc = 21.5 mm"
X5 X6 X7 X8 X9: "TERM BLOCK HDR 4POS 90DEG 3.5MM", Manufacturer="Degson Electronics"
X10: "2,54mm Pitch, 1 Row, 3 Circuits, Vertical, THT"
Y1: library part SJK-6C-25.000-16-30-30-C-50-H, "25.000Мгц, HC-49SM"

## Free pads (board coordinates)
  round 1.6 hole 3 paste-2539.97 mask+1: 3(-36.8,79.3) 3(36.8,79.3)

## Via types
v1: diameter 0.6, hole 0.3, Top Layer to Bottom Layer, tented both sides, 487 vias
v2: diameter 0.8, hole 0.4, Top Layer to Bottom Layer, tented bottom, 1 vias

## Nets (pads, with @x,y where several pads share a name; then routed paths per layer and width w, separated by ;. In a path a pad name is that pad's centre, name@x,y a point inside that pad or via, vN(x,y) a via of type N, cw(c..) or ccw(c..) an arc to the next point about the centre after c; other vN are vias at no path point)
3V3: C16.2 C17.2 C21.2 C26.2 C30.1 C31.1 D3.5 D4.5 DD1.28 DD2.8 DD3.5 DD4.5 DD6.5 L2.2 R12.2 R16.1 R17.1 R19.2 R21.2 R23.2 R24.1 R31.2 R33.2 R36.2 R39.2 X1.9 X1.11 | length 19
  Top Layer w0.3: C31.1@-0.4,51.325 v1(0.475,51.325) ; D3.5@2.281,51.277 2.281,50.47 v1(2.296,50.455) ; D4.5@7.245,51.277 7.245,50.47 v1(7.26,50.455) ; v1(9.1,51.35) 9.104,51.354 C30.1@9.995,51.354 ; DD1.28@9.599,76.193 9.599,77.276 9.449,77.426 9.449,78.342 9.681,78.574 9.973,78.574 v1(10.031,78.631)
  Top Layer w0.6: v1(-27.5,71.825) -26.411,71.825 ccw(c-26.411,71.933) R36.2@-26.303,71.933 ; v1(-18.135,28.305) -18.135,29.038 R16.1@-18.129,29.044 ; v1(-15.426,28.305) -15.426,29.033 R17.1@-15.415,29.044 ; v1(-3.615,77.766) R24.1@-2.343,77.766 ; v1(3.89,80.476) 3.905,80.461 R12.2@3.905,78.917 ; C16.2@24.727,43.024 C16.2@24.742,43.039 ; R31.2@24.88,44.642 24.83,44.592 v1(24.83,43.86) 24.83,43.128 C16.2@24.742,43.039 ; DD6.5@25.122,46.933 25.172,46.883 25.172,46.789 25.724,46.789 v1(25.849,46.665) ; v1(25.225,72.325) 26.091,71.459 R33.2@26.091,69.904 ; L2.2@26.455,43.055 26.44,43.039 v1(25.591,43.039) C16.2@24.742,43.039
  other v1: 26.3,43.8 25.588,43.812 26.32,45.322 26.32,46.113 19.311,66.288 -3.68,69.067 -3.7,70.539 -18.425,72 -3.7,72.275 -16.55,72.725 -18.446,72.813 -3.7,74.758
3V3A: C7.2 C8.2 C9.2 C10.2 C11.2 C12.2 DD1.4 DD1.8 DD1.11 DD1.15 DD1.17 DD1.21 L2.1 R1.2 R2.2 R3.2 | length 24
  Top Layer w0.3: v1(6.998,66.533) 6.998,66.614 7.099,66.715 DD1.4@7.099,67.993 ; DD1.8@9.099,67.993 9.099,66.561 v1(9.129,66.53) ; DD1.11@10.599,67.993 10.599,67.119 10.887,66.831 11.509,66.831 v1(11.55,66.79) ; DD1.15@12.449,70.343 v1(14.415,70.343) ; DD1.17@12.449,71.343 v1(14.446,71.343) ; DD1.21@12.449,73.343 v1(14.669,73.343) ; v1(23.734,39.252) 23.791,39.31 24.003,39.31 24.049,39.356 25.016,39.356 26.025,40.365 26.025,41.39 L2.1@26.225,41.59
  Top Layer w0.6: R2.2@0.234,58.417 R2.2@0.284,58.367 ; R1.2@4.167,58.367 4.174,58.374 v1(4.834,58.374) ; v1(9.129,66.53) 9.425,66.235 C7.2@9.425,65.355 ; v1(11.55,66.79) 12.733,66.79 C11.2@12.911,66.612 ; v1(14.415,70.343) C10.2@15.619,69.139 ; v1(14.446,71.343) 14.476,71.343 14.852,70.967 15.419,70.967 C9.2@15.619,70.767 ; v1(14.669,73.343) 14.865,73.539 15.417,73.539 C8.2@15.617,73.739
  Top Layer w0.7: v1@4.1,64.375 v1(4.101,64.376) 4.101,65.449 C12.2@4.107,65.455 C12.2@4.116,65.446
  other v1: 25.525,39.1 24.65,39.225 25.875,39.775 -1.256,59.164 -0.166,59.174
5V: C15.2 DD6.1 DD6.3 X2.18 X5.4 X10.1 | length 82.1
  Top Layer w0.6: DD6.3@23.172,49.658 DD6.3@23.222,49.608 ; DD6.3@23.222,49.383 DD6.3@23.222,49.608 ; DD6.1@25.122,49.383 25.122,51.534 25.191,51.603 ; X2.18@29.21,54.06 26.753,51.603 25.191,51.603 ; DD6.3@23.222,49.608 23.222,50.726 C15.2@24.099,51.603 25.191,51.603
  Layer 1 w1: X10.1@-9.332,46.096 -6.053,42.816 -6.053,32.39 -3.693,30.031 23.706,30.031 27.436,33.761 27.436,53.711
5V_CAN: C19.1 C24.1 DD3.3 DD4.3 X10.2 | length 44.2
  Top Layer w0.5: C24.1@-20.705,64.758 -20.675,64.788 DD3.3@-20.675,67.057 ; DD3.3@-20.668,67.057 -20.61,67.115 -20.61,68.207 -20.317,68.5 -12.875,68.5 -12.05,69.325 -9.144,69.325 v1(-8.35,68.531) -8.35,68.52 -8.358,68.512 DD4.3@-8.358,67.056 -8.358,66.805 -8.386,66.776 -8.386,64.787 C19.1@-8.415,64.758
  Layer 1 w1: X10.2@-11.872,46.096 -11.872,64.528 -8.35,68.05 v1(-8.35,68.531)
5V_EXT: C28.2 DD5.2 DD5.4 X10.3
12V: C29.2 DD5.3 X6.2 X7.2 X8.2 X9.2
  other v1: -8.243,33.27 -7.425,33.6 -7.4,35.325 -8.4,35.35 -7.375,36.675
ACTLED: DD1.27 R9.2 | length 81.3
  Top Layer w0.3: v1(10.049,77.675) 10.099,77.625 DD1.27@10.099,76.193 ; v1(19.325,36.325) 19.325,35.566 R9.2@19.415,35.476
  Bottom Layer w0.3: v1(10.049,77.675) 10.049,71.954 -4.95,56.955 -4.95,34.175 -2.275,31.5 17.55,31.5 19.325,33.275 v1(19.325,36.325)
AGND: C7.1 C8.1 C9.1 C10.1 C11.1 C12.1 DD1.3 DD1.9 DD1.14 DD1.16 DD1.19 DD1.48 L1.1 R15.1 | length 85.5
  Top Layer w0.3: v1(1.697,64.725) 2.077,65.105 2.557,65.105 C12.1@2.907,65.455 ; DD1.48@4.249,69.343 5.41,69.343 5.5,69.253 v1(5.581,69.253) ; v1(6.547,69.301) 6.599,69.249 DD1.3@6.599,67.993 ; DD1.9@9.599,67.993 9.599,69.292 9.699,69.392 v1(9.699,69.473) ; C7.1@10.825,65.455 11.172,65.108 11.514,65.108 11.784,64.838 11.912,64.838 v1(11.969,64.78) ; v1(11.2,70.978) 11.281,70.978 11.416,70.843 DD1.16@12.449,70.843 ; v1(11.2,72.551) 11.281,72.551 11.489,72.343 DD1.19@12.449,72.343 ; v1(11.261,69.733) 11.342,69.733 11.452,69.843 DD1.14@12.449,69.843 ; v1(24.663,40.456) 24.72,40.514 24.72,41.358 L1.1@24.84,41.478
  Top Layer w0.6: C11.1@14.111,66.612 15.539,66.612 v1(15.542,66.615) ; R15.1@14.211,65.163 R15.1@14.261,65.113 15.503,65.113 v1(15.51,65.106) ; C8.1@16.817,73.739 16.915,73.836 17.793,73.836 v1(17.797,73.84) ; C9.1@16.819,70.767 16.881,70.705 v1(17.984,70.705) ; C10.1@16.853,69.104 v1(17.956,69.104)
  Layer 2 w0.3: 2.884,65.285 2.884,66.722 5.268,69.106 5.352,69.106 5.5,69.253 v1(5.581,69.253) ; v1@5.581,69.336 5.606,69.311 5.85,69.311 5.876,69.336 6.512,69.336 v1(6.547,69.301) ; v1@6.606,69.336 6.7,69.242 9.361,69.242 9.593,69.473 v1(9.699,69.473) 10.92,69.473 11.179,69.733 v1(11.261,69.733) ; v1@11.2,69.851 v1(11.2,70.978) v1@11.2,72.35 ; v1(11.2,72.551) v1@11.2,72.35 ; v1(11.969,64.78) 12.016,64.733 15.056,64.733 15.429,65.106 v1(15.51,65.106) 15.517,65.114 15.517,66.59 v1(15.542,66.615) 15.525,66.632 15.525,68.246 ; 16.075,72.216 15.941,72.35 v1@11.2,72.35 ; v1(17.984,70.705) 15.525,68.246 ; 24.663,42.956 24.581,42.956 24.433,42.808 24.351,42.808 23.739,42.196 22.064,42.196 19.875,44.385 19.875,64.3 15.929,68.246 15.525,68.246
  Layer 2 w0.6: v1(17.797,73.84) 17.778,73.821 16.521,73.821 16.075,73.375 16.075,72.216 16.075,71.056 16.426,70.705 v1(17.984,70.705)
  other v1: 24,40.25
CAN0_N: C27.2 D2.1 DD4.6 R41.1 X8.4 X9.4 | length 64.8
  Top Layer w0.15: DD4.6@-8.358,71.984 -8.358,72.69 -8.773,73.105 -8.773,73.542 -8.773,73.853 -8.244,74.382 R41.1@-8.244,74.707 -8.244,75.032 -8.773,75.561 -8.773,76.115 -8.676,76.212 -8.661,76.212 C27.2@-8.236,76.637 -8.661,77.062 -8.672,77.062 -8.759,77.15 -8.759,77.718 -8.231,78.246 -8.231,79.503 -8.751,80.023 -8.751,80.543 -8.663,80.631 D2.1@-8.351,80.631 ; D2.1@-8.065,81.006 -8.065,81.056 -8.39,81.381 -8.44,81.381 -8.875,81.816 -8.875,87.093 cw(c-7.318,87.093) -8.419,88.194 cw(c-7.801,87.576) -7.801,88.45 1.99,88.45 ccw(c1.99,89.71) 2.881,88.819 ccw(c1.93,89.77) 3.275,89.77 3.275,92.401 X9.4@4.871,93.998
  Bottom Layer w0.15: X9.4@4.871,93.998 4.514,94.354 3.654,94.354 3.194,94.815 3.194,96.15 cw(c4.394,96.15) 4.394,97.35 7.075,97.35 cw(c7.075,96.4) 8.025,96.4 8.025,92.875 ccw(c9.325,92.875) 9.325,91.575 19.5,91.575 ccw(c19.5,92.375) 20.3,92.375 20.3,93.263 20.698,93.661 21.547,93.661 X8.4@21.909,94.023
CAN0_P: C23.1 D2.2 DD4.7 R40.1 X8.3 X9.3 | length 64.7
  Top Layer w0.15: D2.2@-9.965,81.006 -9.965,81.056 -9.64,81.381 -9.59,81.381 -9.175,81.795 -9.175,87.093 cw(c-7.318,87.093) -8.631,88.406 cw(c-7.801,87.576) -7.801,88.75 1.99,88.75 ccw(c1.99,89.71) 2.669,89.031 ccw(c1.93,89.77) 2.975,89.77 2.975,92.388 X9.3@1.366,93.998 ; DD4.7@-9.628,71.984 -9.628,72.69 -9.223,73.095 -9.223,73.356 -9.223,73.853 -9.752,74.382 R40.1@-9.752,74.707 -9.752,75.032 -9.223,75.561 -9.223,76.124 -9.311,76.212 -9.317,76.212 C23.1@-9.742,76.637 -9.317,77.062 -9.302,77.062 -9.209,77.155 -9.209,77.744 -9.738,78.272 -9.738,79.529 -9.201,80.065 -9.201,80.331 -9.201,80.543 -9.289,80.631 D2.2@-9.601,80.631
  Bottom Layer w0.15: X9.3@1.366,93.998 1.757,94.388 2.549,94.388 2.894,94.733 2.894,96.15 cw(c4.394,96.15) 4.394,97.65 7.075,97.65 cw(c7.075,96.4) 8.325,96.4 8.325,92.875 ccw(c9.325,92.875) 9.325,91.875 19.5,91.875 ccw(c19.5,92.375) 20,92.375 20,93.263 19.609,93.654 18.773,93.654 X8.3@18.404,94.023
CAN0_RX/PA15: DD4.4 R47.1 | length 3.7
  Top Layer w0.2: DD4.4@-7.072,66.821 -7.088,66.805 -7.088,65.663 -6.845,65.42 R47.1@-5.319,65.42
  Top Layer w0.55: DD4.4@-7.084,66.821 DD4.4@-7.084,67.523
CAN0_TX/PA14: DD4.1 R46.1 | length 3.9
  Top Layer w0.2: R46.1@-13.191,65.387 -13.129,65.325 -11.075,65.325 -10.898,65.502 DD4.1@-10.898,67.056
CAN1_N: C22.2 D1.1 DD3.6 R38.1 X6.4 X7.4 | length 60.2
  Top Layer w0.15: DD3.6@-20.573,71.984 -20.573,72.69 -20.988,73.105 -20.988,73.542 -20.988,73.853 -20.459,74.382 -20.459,75.032 -20.988,75.561 -20.988,76.115 -20.891,76.212 -20.876,76.212 -20.451,76.637 -20.876,77.062 -20.886,77.062 -20.974,77.15 -20.974,77.718 -20.446,78.246 -20.446,79.503 -20.966,80.023 -20.966,80.543 -20.878,80.631 D1.1@-20.566,80.631 ; D1.1@-20.279,81.006 -20.279,81.056 -20.604,81.381 -20.654,81.381 -21.083,81.81 -21.083,87.242 cw(c-20.3,87.242) -20.3,88.025 -15.075,88.025 ccw(c-15.075,89.525) -13.575,89.525 -13.575,92.388 X7.4@-11.966,93.998
  Bottom Layer w0.15: X6.4@-29.074,93.998 -29.576,93.998 -30.725,92.848 -30.725,91.85 ccw(c-30.45,91.85) -30.45,91.575 -27.075,91.575 ccw(c-27.075,92.85) -25.8,92.85 -25.8,95.55 cw(c-23.75,95.55) -23.75,97.6 -14.593,97.6 cw(c-14.593,96.65) -13.643,96.65 -13.643,95.16 -12.481,93.998 X7.4@-11.966,93.998
CAN1_P: C18.1 D1.2 DD3.7 R37.1 X6.3 X7.3 | length 59.9
  Top Layer w0.15: D1.2@-22.179,81.006 -22.179,81.056 -21.854,81.381 -21.804,81.381 -21.383,81.802 -21.383,87.242 cw(c-20.3,87.242) -20.3,88.325 -15.075,88.325 ccw(c-15.075,89.525) -13.875,89.525 -13.875,92.402 X7.3@-15.471,93.998 ; DD3.7@-21.843,71.984 -21.843,72.69 -21.438,73.095 -21.438,73.356 -21.438,73.853 -21.967,74.382 -21.967,75.032 -21.438,75.561 -21.438,76.124 -21.526,76.212 -21.532,76.212 -21.957,76.637 -21.532,77.062 -21.517,77.062 -21.424,77.155 -21.424,77.744 -21.952,78.272 -21.952,79.529 -21.416,80.065 -21.416,80.331 -21.416,80.543 -21.504,80.631 D1.2@-21.816,80.631
  Bottom Layer w0.15: X6.3@-32.579,93.998 -32.167,93.998 -31.025,92.855 -31.025,91.85 ccw(c-30.45,91.85) -30.45,91.275 -27.075,91.275 ccw(c-27.075,92.85) -25.5,92.85 -25.5,95.55 cw(c-23.75,95.55) -23.75,97.3 -14.593,97.3 cw(c-14.593,96.65) -13.943,96.65 -13.943,95.162 -15.107,93.998 X7.3@-15.471,93.998
CAN1_RX/PB7: DD3.4 R50.1 | length 3.5
  Top Layer w0.2: DD3.4@-19.369,67.057 -19.269,66.957 -19.269,65.442 -19.152,65.325 -17.559,65.325 R50.1@-17.464,65.42
CAN1_TX/PB6: DD3.1 R49.1 | length 3.8
  Top Layer w0.2: R49.1@-25.208,65.302 -25.182,65.275 -23.296,65.275 -23.179,65.392 DD3.1@-23.179,67.057
CANBus0_STB: DD4.8 R39.1 R48.1 | length 3.1
  Top Layer w0.2: R48.1@-12.413,70.449 -12.413,71.883 R39.1@-12.447,71.917 -10.965,71.917 DD4.8@-10.898,71.984
CANBus1_STB: DD3.8 R36.1 R51.1 | length 3.2
  Top Layer w0.2: R51.1@-24.913,70.47 -24.913,71.923 R36.1@-24.903,71.933 -24.852,71.984 DD3.8@-23.179,71.984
